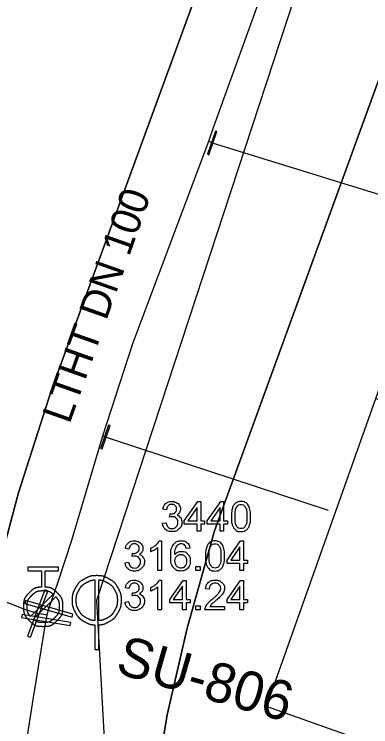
# Model space of a CAD drawing. Extents: x -562248 to -562040, y -1079385 to -1079027.
# Drawn here: x -562129.79 to -562111.72, y -1079101.77 to -1079065.59 of the extents above; entities that cross this region are included whole.
import ezdxf

# ---------------------------------------------------------------- set-up
doc = ezdxf.new("R2010")
doc.units = 0
for name, color, linetype in [('Armatura - popis', 7, 'Continuous'), ('Armatura vodovodní', 7, 'Continuous'), ('Default', 7, 'Continuous'), ('Hydrant', 7, 'Continuous'), ('Kanalizační stoka', 7, 'Continuous'), ('Kanalizační šachta', 7, 'Continuous'), ('Parcela-polygon', 7, 'Continuous'), ('Popis šachty', 7, 'Continuous'), ('Vodovodní přípojka', 7, 'Continuous'), ('Vodovodní řad', 7, 'Continuous'), ('Řad vodovodní popis', 7, 'Continuous')]:
    doc.layers.add(name, color=color, linetype=linetype)

msp = doc.modelspace()

# ---------------------------------------------------------------- linework, layer by layer
at = {"layer": 'Armatura vodovodní'}
for points in [[(-562119.926, -1079072.73), (-562119.517, -1079071.549), (-562119.59, -1079071.523), (-562120, -1079072.704)], [(-562125.345, -1079087.662), (-562124.936, -1079086.481), (-562125.009, -1079086.455), (-562125.419, -1079087.636)], [(-562128.97, -1079097.226), (-562128.101, -1079094.882), (-562128.247, -1079094.828), (-562129.116, -1079097.172)], [(-562126.863, -1079096.212), (-562126.819, -1079096.062), (-562129.221, -1079095.369), (-562129.264, -1079095.519)], [(-562126.954, -1079096.629), (-562126.929, -1079096.475), (-562129.396, -1079096.071), (-562129.421, -1079096.226)]]:
    msp.add_lwpolyline(points, close=True, dxfattribs=at)
at = {"layer": 'Default'}
for points in [[(-562126.225, -1079094.261), (-562126.424, -1079094.369), (-562126.579, -1079094.522), (-562126.692, -1079094.723)], [(-562125.61, -1079094.1), (-562125.822, -1079094.1), (-562126.027, -1079094.154), (-562126.225, -1079094.261)], [(-562126.125, -1079094.444), (-562125.982, -1079094.368), (-562125.844, -1079094.324), (-562125.713, -1079094.312)], [(-562124.996, -1079094.261), (-562125.195, -1079094.154), (-562125.4, -1079094.1), (-562125.61, -1079094.1)], [(-562125.507, -1079094.312), (-562125.376, -1079094.324), (-562125.239, -1079094.368), (-562125.097, -1079094.444)], [(-562124.528, -1079094.723), (-562124.641, -1079094.522), (-562124.797, -1079094.369), (-562124.996, -1079094.261)], [(-562128.42, -1079094.678), (-562128.658, -1079094.696), (-562128.863, -1079094.792), (-562129.035, -1079094.967)], [(-562127.617, -1079094.967), (-562127.789, -1079094.794), (-562127.994, -1079094.697), (-562128.232, -1079094.678)], [(-562126.513, -1079094.829), (-562126.421, -1079094.662), (-562126.291, -1079094.534), (-562126.125, -1079094.444)], [(-562125.097, -1079094.444), (-562124.931, -1079094.534), (-562124.801, -1079094.662), (-562124.708, -1079094.829)], [(-562129.035, -1079094.967), (-562129.229, -1079095.162), (-562129.326, -1079095.399), (-562129.326, -1079095.676)], [(-562128.903, -1079095.097), (-562128.745, -1079094.939), (-562128.553, -1079094.86), (-562128.328, -1079094.86)], [(-562128.328, -1079094.86), (-562128.134, -1079094.86), (-562127.965, -1079094.918), (-562127.82, -1079095.035)], [(-562127.326, -1079095.676), (-562127.326, -1079095.399), (-562127.423, -1079095.162), (-562127.617, -1079094.967)], [(-562126.692, -1079094.723), (-562126.804, -1079094.923), (-562126.86, -1079095.132), (-562126.86, -1079095.35)], [(-562126.652, -1079095.35), (-562126.652, -1079095.169), (-562126.606, -1079094.996), (-562126.513, -1079094.829)], [(-562124.708, -1079094.829), (-562124.614, -1079094.996), (-562124.568, -1079095.169), (-562124.568, -1079095.35)], [(-562124.36, -1079095.35), (-562124.36, -1079095.132), (-562124.416, -1079094.923), (-562124.528, -1079094.723)], [(-562129.14, -1079095.672), (-562129.14, -1079095.447), (-562129.061, -1079095.255), (-562128.903, -1079095.097)], [(-562127.687, -1079095.168), (-562127.573, -1079095.311), (-562127.515, -1079095.479), (-562127.515, -1079095.672)], [(-562126.86, -1079095.35), (-562126.86, -1079095.566), (-562126.805, -1079095.774), (-562126.695, -1079095.973)], [(-562126.516, -1079095.868), (-562126.607, -1079095.703), (-562126.652, -1079095.531), (-562126.652, -1079095.35)], [(-562124.568, -1079095.35), (-562124.568, -1079095.531), (-562124.613, -1079095.703), (-562124.704, -1079095.868)], [(-562124.525, -1079095.973), (-562124.415, -1079095.774), (-562124.36, -1079095.566), (-562124.36, -1079095.35)], [(-562129.326, -1079095.676), (-562129.326, -1079095.952), (-562129.228, -1079096.187), (-562129.033, -1079096.382)], [(-562128.965, -1079096.18), (-562129.082, -1079096.035), (-562129.14, -1079095.866), (-562129.14, -1079095.672)], [(-562127.515, -1079095.672), (-562127.515, -1079095.897), (-562127.595, -1079096.089), (-562127.754, -1079096.247)], [(-562127.619, -1079096.382), (-562127.424, -1079096.187), (-562127.326, -1079095.952), (-562127.326, -1079095.676)], [(-562126.695, -1079095.973), (-562126.585, -1079096.171), (-562126.431, -1079096.325), (-562126.233, -1079096.434)], [(-562126.13, -1079096.251), (-562126.296, -1079096.16), (-562126.425, -1079096.032), (-562126.516, -1079095.868)], [(-562124.704, -1079095.868), (-562124.795, -1079096.032), (-562124.923, -1079096.16), (-562125.088, -1079096.251)], [(-562124.987, -1079096.434), (-562124.789, -1079096.325), (-562124.635, -1079096.171), (-562124.525, -1079095.973)], [(-562129.033, -1079096.382), (-562128.838, -1079096.577), (-562128.603, -1079096.674), (-562128.328, -1079096.674)], [(-562128.328, -1079096.485), (-562128.521, -1079096.485), (-562128.689, -1079096.427), (-562128.832, -1079096.313)], [(-562127.754, -1079096.247), (-562127.913, -1079096.405), (-562128.104, -1079096.485), (-562128.328, -1079096.485)], [(-562128.328, -1079096.674), (-562128.051, -1079096.674), (-562127.814, -1079096.577), (-562127.619, -1079096.382)], [(-562126.233, -1079096.434), (-562126.058, -1079096.532), (-562125.885, -1079096.586), (-562125.713, -1079096.598)], [(-562125.713, -1079096.385), (-562125.849, -1079096.375), (-562125.988, -1079096.331), (-562126.13, -1079096.251)], [(-562125.088, -1079096.251), (-562125.231, -1079096.331), (-562125.371, -1079096.375), (-562125.507, -1079096.385)], [(-562125.507, -1079096.598), (-562125.335, -1079096.586), (-562125.162, -1079096.532), (-562124.987, -1079096.434)]]:
    msp.add_open_spline(points, degree=2, dxfattribs=at)
at = {"layer": 'Hydrant'}
for points in [[(-562128.232, -1079094.678), (-562128.232, -1079093.861), (-562127.545, -1079093.861), (-562127.545, -1079093.674), (-562129.107, -1079093.674), (-562129.107, -1079093.861), (-562128.42, -1079093.861), (-562128.42, -1079094.678)], [(-562127.82, -1079095.035), (-562128.965, -1079096.18)], [(-562128.832, -1079096.313), (-562127.687, -1079095.168)]]:
    msp.add_lwpolyline(points, dxfattribs=at)
at = {"layer": 'Kanalizační stoka'}
for points in [[(-562125.61, -1079095.35), (-562111.98, -1079053.75)], [(-562123.19, -1079139.07), (-562125.61, -1079095.35)]]:
    msp.add_lwpolyline(points, dxfattribs=at)
at = {"layer": 'Kanalizační šachta'}
for points in [[(-562125.713, -1079094.312), (-562125.713, -1079096.385)], [(-562125.507, -1079096.385), (-562125.507, -1079094.312)], [(-562125.713, -1079097.85), (-562125.507, -1079097.85), (-562125.507, -1079096.598)], [(-562125.713, -1079096.598), (-562125.713, -1079097.85)]]:
    msp.add_lwpolyline(points, dxfattribs=at)
at = {"layer": 'Parcela-polygon'}
for points in [[(-562150.044, -1079089.409), (-562131.3, -1079096.35), (-562129.6, -1079089.95), (-562127.9, -1079084.66), (-562116.47, -1079053.33), (-562116.62, -1079052.94), (-562134.941, -1079046.267)], [(-562122.69, -1079105.05), (-562122.05, -1079101.16), (-562121.03, -1079096.76), (-562119.65, -1079091.82), (-562106.84, -1079056.62), (-562116.62, -1079052.94), (-562116.47, -1079053.33), (-562127.9, -1079084.66), (-562129.6, -1079089.95), (-562131.3, -1079096.35), (-562132.29, -1079100.17), (-562132.68, -1079103.22)], [(-562089.427, -1079062.836), (-562106.84, -1079056.62), (-562119.65, -1079091.82), (-562121.03, -1079096.76), (-562122.05, -1079101.16), (-562122.69, -1079105.05), (-562122.92, -1079108.96), (-562097.98, -1079104.526)], [(-562117.01, -1079100.74), (-562111.46, -1079085.11), (-562105.93, -1079069.43), (-562096.89, -1079072.69), (-562102.44, -1079088.31), (-562107.99, -1079103.94), (-562117.01, -1079100.74)]]:
    msp.add_lwpolyline(points, dxfattribs=at)
msp.add_lwpolyline([(-562111.46, -1079085.11), (-562102.44, -1079088.31), (-562107.99, -1079103.94), (-562117.01, -1079100.74)], close=True, dxfattribs=at)
at = {"layer": 'Popis šachty'}
for points in [[(-562120.527, -1079091.838), (-562120.527, -1079091.479), (-562121.178, -1079091.479), (-562121.178, -1079091.31), (-562120.494, -1079090.338), (-562120.343, -1079090.338), (-562120.343, -1079091.31), (-562120.141, -1079091.31), (-562120.141, -1079091.479), (-562120.343, -1079091.479), (-562120.343, -1079091.838), (-562120.527, -1079091.838)], [(-562119.362, -1079091.838), (-562119.362, -1079091.479), (-562120.013, -1079091.479), (-562120.013, -1079091.31), (-562119.329, -1079090.338), (-562119.178, -1079090.338), (-562119.178, -1079091.31), (-562118.976, -1079091.31), (-562118.976, -1079091.479), (-562119.178, -1079091.479), (-562119.178, -1079091.838), (-562119.362, -1079091.838)], [(-562122.079, -1079090.755), (-562122.263, -1079090.721)], [(-562120.527, -1079091.31), (-562120.527, -1079090.633), (-562120.997, -1079091.31), (-562120.527, -1079091.31)], [(-562119.362, -1079091.31), (-562119.362, -1079090.633), (-562119.832, -1079091.31), (-562119.362, -1079091.31)], [(-562121.918, -1079091.127), (-562121.898, -1079090.966)], [(-562122.281, -1079091.441), (-562122.097, -1079091.417)], [(-562122.442, -1079092.333), (-562122.323, -1079092.333), (-562122.323, -1079093.838)], [(-562118.349, -1079093.838), (-562118.349, -1079093.479), (-562119, -1079093.479), (-562119, -1079093.31), (-562118.316, -1079092.338), (-562118.165, -1079092.338), (-562118.165, -1079093.31), (-562117.963, -1079093.31), (-562117.963, -1079093.479), (-562118.165, -1079093.479), (-562118.165, -1079093.838), (-562118.349, -1079093.838)], [(-562123.978, -1079092.755), (-562124.162, -1079092.721)], [(-562122.876, -1079092.887), (-562122.876, -1079092.709)], [(-562122.323, -1079093.838), (-562122.507, -1079093.838), (-562122.507, -1079092.665)], [(-562120.894, -1079092.707), (-562121.077, -1079092.721)], [(-562118.349, -1079093.31), (-562118.349, -1079092.633), (-562118.819, -1079093.31), (-562118.349, -1079093.31)], [(-562123.817, -1079093.127), (-562123.797, -1079092.966)], [(-562124.18, -1079093.441), (-562123.996, -1079093.417)], [(-562120.583, -1079093.838), (-562120.583, -1079093.629), (-562120.374, -1079093.629), (-562120.374, -1079093.838), (-562120.583, -1079093.838)], [(-562122.442, -1079094.333), (-562122.323, -1079094.333), (-562122.323, -1079095.838)], [(-562121.261, -1079095.838), (-562121.261, -1079095.479), (-562121.912, -1079095.479), (-562121.912, -1079095.31), (-562121.228, -1079094.338), (-562121.077, -1079094.338), (-562121.077, -1079095.31), (-562120.875, -1079095.31), (-562120.875, -1079095.479), (-562121.077, -1079095.479), (-562121.077, -1079095.838), (-562121.261, -1079095.838)], [(-562118.349, -1079095.838), (-562118.349, -1079095.479), (-562119, -1079095.479), (-562119, -1079095.31), (-562118.316, -1079094.338), (-562118.165, -1079094.338), (-562118.165, -1079095.31), (-562117.963, -1079095.31), (-562117.963, -1079095.479), (-562118.165, -1079095.479), (-562118.165, -1079095.838), (-562118.349, -1079095.838)], [(-562122.323, -1079095.838), (-562122.507, -1079095.838), (-562122.507, -1079094.665)], [(-562121.261, -1079095.31), (-562121.261, -1079094.633), (-562121.731, -1079095.31), (-562121.261, -1079095.31)], [(-562118.349, -1079095.31), (-562118.349, -1079094.633), (-562118.819, -1079095.31), (-562118.349, -1079095.31)], [(-562123.978, -1079094.755), (-562124.162, -1079094.721)], [(-562123.817, -1079095.127), (-562123.797, -1079094.966)], [(-562122.876, -1079094.887), (-562122.876, -1079094.709)], [(-562119.904, -1079094.785), (-562120.094, -1079094.766)], [(-562124.18, -1079095.441), (-562123.996, -1079095.417)], [(-562120.583, -1079095.838), (-562120.583, -1079095.629), (-562120.374, -1079095.629), (-562120.374, -1079095.838), (-562120.583, -1079095.838)], [(-562119.137, -1079095.661), (-562119.137, -1079095.838), (-562120.128, -1079095.838)], [(-562119.872, -1079095.661), (-562119.137, -1079095.661)]]:
    msp.add_lwpolyline(points, dxfattribs=at)
for points in [[(-562122.263, -1079090.721), (-562122.229, -1079090.536), (-562122.109, -1079090.435), (-562121.99, -1079090.333), (-562121.812, -1079090.333), (-562121.689, -1079090.333), (-562121.585, -1079090.385), (-562121.482, -1079090.438), (-562121.427, -1079090.529), (-562121.372, -1079090.62), (-562121.372, -1079090.722), (-562121.372, -1079090.819), (-562121.425, -1079090.899), (-562121.477, -1079090.978), (-562121.579, -1079091.025), (-562121.446, -1079091.056), (-562121.373, -1079091.153), (-562121.299, -1079091.249), (-562121.299, -1079091.394), (-562121.299, -1079091.591), (-562121.442, -1079091.727), (-562121.586, -1079091.864), (-562121.805, -1079091.864), (-562122.002, -1079091.864), (-562122.132, -1079091.746), (-562122.263, -1079091.628), (-562122.281, -1079091.441)], [(-562118.787, -1079091.099), (-562118.787, -1079090.833), (-562118.733, -1079090.67), (-562118.678, -1079090.508), (-562118.57, -1079090.42), (-562118.462, -1079090.333), (-562118.299, -1079090.333), (-562118.178, -1079090.333), (-562118.087, -1079090.381), (-562117.995, -1079090.43), (-562117.936, -1079090.521), (-562117.877, -1079090.613), (-562117.844, -1079090.744), (-562117.81, -1079090.876), (-562117.81, -1079091.099), (-562117.81, -1079091.363), (-562117.864, -1079091.525), (-562117.918, -1079091.687), (-562118.026, -1079091.775), (-562118.134, -1079091.864), (-562118.299, -1079091.864), (-562118.515, -1079091.864), (-562118.639, -1079091.709), (-562118.787, -1079091.521), (-562118.787, -1079091.099)], [(-562121.898, -1079090.966), (-562121.879, -1079090.968), (-562121.868, -1079090.968), (-562121.75, -1079090.968), (-562121.656, -1079090.907), (-562121.562, -1079090.846), (-562121.562, -1079090.718), (-562121.562, -1079090.617), (-562121.631, -1079090.55), (-562121.699, -1079090.484), (-562121.808, -1079090.484), (-562121.915, -1079090.484), (-562121.987, -1079090.551), (-562122.058, -1079090.619), (-562122.079, -1079090.755)], [(-562118.598, -1079091.099), (-562118.598, -1079091.469), (-562118.511, -1079091.591), (-562118.425, -1079091.713), (-562118.299, -1079091.713), (-562118.172, -1079091.713), (-562118.086, -1079091.59), (-562118, -1079091.468), (-562118, -1079091.099), (-562118, -1079090.728), (-562118.086, -1079090.607), (-562118.172, -1079090.485), (-562118.301, -1079090.485), (-562118.427, -1079090.485), (-562118.503, -1079090.592), (-562118.598, -1079090.729), (-562118.598, -1079091.099)], [(-562122.097, -1079091.417), (-562122.066, -1079091.573), (-562121.99, -1079091.642), (-562121.914, -1079091.712), (-562121.804, -1079091.712), (-562121.673, -1079091.712), (-562121.584, -1079091.622), (-562121.495, -1079091.531), (-562121.495, -1079091.398), (-562121.495, -1079091.272), (-562121.578, -1079091.189), (-562121.66, -1079091.107), (-562121.788, -1079091.107), (-562121.84, -1079091.107), (-562121.918, -1079091.127)], [(-562124.162, -1079092.721), (-562124.128, -1079092.536), (-562124.008, -1079092.435), (-562123.889, -1079092.333), (-562123.71, -1079092.333), (-562123.588, -1079092.333), (-562123.484, -1079092.385), (-562123.381, -1079092.438), (-562123.326, -1079092.529), (-562123.271, -1079092.62), (-562123.271, -1079092.722), (-562123.271, -1079092.819), (-562123.323, -1079092.899), (-562123.376, -1079092.978), (-562123.478, -1079093.025), (-562123.345, -1079093.056), (-562123.271, -1079093.153), (-562123.198, -1079093.249), (-562123.198, -1079093.394), (-562123.198, -1079093.591), (-562123.341, -1079093.727), (-562123.484, -1079093.864), (-562123.703, -1079093.864), (-562123.901, -1079093.864), (-562124.031, -1079093.746), (-562124.162, -1079093.628), (-562124.18, -1079093.441)], [(-562123.797, -1079092.966), (-562123.778, -1079092.968), (-562123.767, -1079092.968), (-562123.649, -1079092.968), (-562123.555, -1079092.907), (-562123.461, -1079092.846), (-562123.461, -1079092.718), (-562123.461, -1079092.617), (-562123.53, -1079092.55), (-562123.598, -1079092.484), (-562123.707, -1079092.484), (-562123.814, -1079092.484), (-562123.886, -1079092.551), (-562123.957, -1079092.619), (-562123.978, -1079092.755)], [(-562122.876, -1079092.709), (-562122.721, -1079092.637), (-562122.606, -1079092.533), (-562122.49, -1079092.43), (-562122.442, -1079092.333)], [(-562121.077, -1079092.721), (-562121.102, -1079092.612), (-562121.147, -1079092.563), (-562121.222, -1079092.484), (-562121.332, -1079092.484), (-562121.42, -1079092.484), (-562121.487, -1079092.533), (-562121.574, -1079092.596), (-562121.624, -1079092.718), (-562121.674, -1079092.84), (-562121.676, -1079093.065), (-562121.61, -1079092.964), (-562121.513, -1079092.915), (-562121.417, -1079092.866), (-562121.312, -1079092.866), (-562121.127, -1079092.866), (-562120.998, -1079093.001), (-562120.868, -1079093.137), (-562120.868, -1079093.351), (-562120.868, -1079093.492), (-562120.929, -1079093.614), (-562120.99, -1079093.735), (-562121.096, -1079093.799), (-562121.203, -1079093.864), (-562121.338, -1079093.864), (-562121.568, -1079093.864), (-562121.714, -1079093.694), (-562121.859, -1079093.525), (-562121.859, -1079093.137), (-562121.859, -1079092.702), (-562121.698, -1079092.505), (-562121.558, -1079092.333), (-562121.32, -1079092.333), (-562121.143, -1079092.333), (-562121.03, -1079092.432), (-562120.917, -1079092.531), (-562120.894, -1079092.707)], [(-562120.104, -1079093.099), (-562120.104, -1079092.833), (-562120.05, -1079092.67), (-562119.995, -1079092.508), (-562119.887, -1079092.42), (-562119.779, -1079092.333), (-562119.616, -1079092.333), (-562119.495, -1079092.333), (-562119.404, -1079092.381), (-562119.312, -1079092.43), (-562119.253, -1079092.521), (-562119.194, -1079092.613), (-562119.161, -1079092.744), (-562119.127, -1079092.876), (-562119.127, -1079093.099), (-562119.127, -1079093.363), (-562119.181, -1079093.525), (-562119.235, -1079093.687), (-562119.343, -1079093.775), (-562119.451, -1079093.864), (-562119.616, -1079093.864), (-562119.832, -1079093.864), (-562119.956, -1079093.709), (-562120.104, -1079093.521), (-562120.104, -1079093.099)], [(-562119.915, -1079093.099), (-562119.915, -1079093.469), (-562119.828, -1079093.591), (-562119.742, -1079093.713), (-562119.616, -1079093.713), (-562119.489, -1079093.713), (-562119.403, -1079093.59), (-562119.317, -1079093.468), (-562119.317, -1079093.099), (-562119.317, -1079092.728), (-562119.403, -1079092.607), (-562119.489, -1079092.485), (-562119.618, -1079092.485), (-562119.744, -1079092.485), (-562119.82, -1079092.592), (-562119.915, -1079092.729), (-562119.915, -1079093.099)], [(-562122.507, -1079092.665), (-562122.574, -1079092.729), (-562122.682, -1079092.792), (-562122.79, -1079092.855), (-562122.876, -1079092.887)], [(-562123.996, -1079093.417), (-562123.964, -1079093.573), (-562123.888, -1079093.642), (-562123.813, -1079093.712), (-562123.702, -1079093.712), (-562123.572, -1079093.712), (-562123.483, -1079093.622), (-562123.394, -1079093.531), (-562123.394, -1079093.398), (-562123.394, -1079093.272), (-562123.476, -1079093.189), (-562123.559, -1079093.107), (-562123.687, -1079093.107), (-562123.739, -1079093.107), (-562123.817, -1079093.127)], [(-562121.648, -1079093.352), (-562121.648, -1079093.448), (-562121.607, -1079093.535), (-562121.567, -1079093.622), (-562121.495, -1079093.667), (-562121.422, -1079093.713), (-562121.342, -1079093.713), (-562121.225, -1079093.713), (-562121.141, -1079093.619), (-562121.058, -1079093.524), (-562121.058, -1079093.363), (-562121.058, -1079093.207), (-562121.14, -1079093.117), (-562121.223, -1079093.028), (-562121.349, -1079093.028), (-562121.474, -1079093.028), (-562121.561, -1079093.117), (-562121.648, -1079093.207), (-562121.648, -1079093.352)], [(-562124.162, -1079094.721), (-562124.128, -1079094.536), (-562124.008, -1079094.435), (-562123.889, -1079094.333), (-562123.71, -1079094.333), (-562123.588, -1079094.333), (-562123.484, -1079094.385), (-562123.381, -1079094.438), (-562123.326, -1079094.529), (-562123.271, -1079094.62), (-562123.271, -1079094.722), (-562123.271, -1079094.819), (-562123.323, -1079094.899), (-562123.376, -1079094.978), (-562123.478, -1079095.025), (-562123.345, -1079095.056), (-562123.271, -1079095.153), (-562123.198, -1079095.249), (-562123.198, -1079095.394), (-562123.198, -1079095.591), (-562123.341, -1079095.727), (-562123.484, -1079095.864), (-562123.703, -1079095.864), (-562123.901, -1079095.864), (-562124.031, -1079095.746), (-562124.162, -1079095.628), (-562124.18, -1079095.441)], [(-562122.876, -1079094.709), (-562122.721, -1079094.637), (-562122.606, -1079094.533), (-562122.49, -1079094.43), (-562122.442, -1079094.333)], [(-562120.094, -1079094.766), (-562120.075, -1079094.554), (-562119.948, -1079094.444), (-562119.821, -1079094.333), (-562119.607, -1079094.333), (-562119.391, -1079094.333), (-562119.265, -1079094.452), (-562119.139, -1079094.572), (-562119.139, -1079094.749), (-562119.139, -1079094.839), (-562119.176, -1079094.926), (-562119.213, -1079095.013), (-562119.298, -1079095.109), (-562119.384, -1079095.205), (-562119.582, -1079095.373), (-562119.747, -1079095.512), (-562119.795, -1079095.561), (-562119.842, -1079095.611), (-562119.872, -1079095.661)], [(-562123.797, -1079094.966), (-562123.778, -1079094.968), (-562123.767, -1079094.968), (-562123.649, -1079094.968), (-562123.555, -1079094.907), (-562123.461, -1079094.846), (-562123.461, -1079094.718), (-562123.461, -1079094.617), (-562123.53, -1079094.55), (-562123.598, -1079094.484), (-562123.707, -1079094.484), (-562123.814, -1079094.484), (-562123.886, -1079094.551), (-562123.957, -1079094.619), (-562123.978, -1079094.755)], [(-562122.507, -1079094.665), (-562122.574, -1079094.729), (-562122.682, -1079094.792), (-562122.79, -1079094.855), (-562122.876, -1079094.887)], [(-562120.128, -1079095.838), (-562120.13, -1079095.772), (-562120.107, -1079095.71), (-562120.069, -1079095.609), (-562119.985, -1079095.511), (-562119.902, -1079095.413), (-562119.745, -1079095.284), (-562119.5, -1079095.083), (-562119.415, -1079094.966), (-562119.329, -1079094.849), (-562119.329, -1079094.745), (-562119.329, -1079094.635), (-562119.407, -1079094.56), (-562119.485, -1079094.485), (-562119.611, -1079094.485), (-562119.744, -1079094.485), (-562119.824, -1079094.565), (-562119.903, -1079094.644), (-562119.904, -1079094.785)], [(-562123.996, -1079095.417), (-562123.964, -1079095.573), (-562123.888, -1079095.642), (-562123.813, -1079095.712), (-562123.702, -1079095.712), (-562123.572, -1079095.712), (-562123.483, -1079095.622), (-562123.394, -1079095.531), (-562123.394, -1079095.398), (-562123.394, -1079095.272), (-562123.476, -1079095.189), (-562123.559, -1079095.107), (-562123.687, -1079095.107), (-562123.739, -1079095.107), (-562123.817, -1079095.127)]]:
    msp.add_open_spline(points, degree=3, dxfattribs=at)
at = {"layer": 'Vodovodní přípojka'}
for points in [[(-562119.925, -1079072.045), (-562119.759, -1079072.126), (-562108.493, -1079075.605)], [(-562125.308, -1079086.997), (-562125.178, -1079087.058), (-562124.735, -1079087.205), (-562113.88, -1079090.777)]]:
    msp.add_lwpolyline(points, dxfattribs=at)
at = {"layer": 'Vodovodní řad'}
for points in [[(-562128.126, -1079096.082), (-562128.042, -1079095.79), (-562127.563, -1079094.412), (-562126.882, -1079092.296), (-562125.308, -1079086.997), (-562123.784, -1079082.313), (-562119.925, -1079072.045), (-562119.675, -1079071.286), (-562115.714, -1079060.331), (-562112.61, -1079051.657), (-562112.242, -1079050.849)], [(-562128.13, -1079096.11), (-562128.608, -1079096.027), (-562129.262, -1079095.825), (-562131.937, -1079094.765), (-562138.471, -1079092.308), (-562147.354, -1079088.946), (-562149.623, -1079088.208)], [(-562104.508, -1079195.68), (-562105.675, -1079193.599), (-562106.045, -1079192.495), (-562108.292, -1079185.845), (-562110.54, -1079179.194), (-562111.609, -1079176.901), (-562113.474, -1079171.283), (-562115.559, -1079165.192), (-562118.308, -1079157.281), (-562119.874, -1079152.505), (-562123.128, -1079142.718), (-562124.818, -1079137.317), (-562126.048, -1079133.176), (-562126.972, -1079129.683), (-562127.886, -1079125.317), (-562128.484, -1079121.808), (-562129.183, -1079117.074), (-562129.389, -1079112.24), (-562129.474, -1079106.997), (-562129.319, -1079103.524), (-562128.819, -1079100.288), (-562128.175, -1079096.35), (-562128.115, -1079096.032)]]:
    msp.add_lwpolyline(points, dxfattribs=at)

# ---------------------------------------------------------------- texts
at = {"layer": 'Armatura - popis'}
msp.add_text('SU-806', height=2, rotation=343.8941, dxfattribs=at).set_placement((-562124.727, -1079099.024))
at = {"layer": 'Řad vodovodní popis'}
msp.add_text('LTHT DN 100', height=1.5, rotation=70.4779, dxfattribs=at).set_placement((-562126.993, -1079086.444))

doc.saveas('drawing.dxf')
